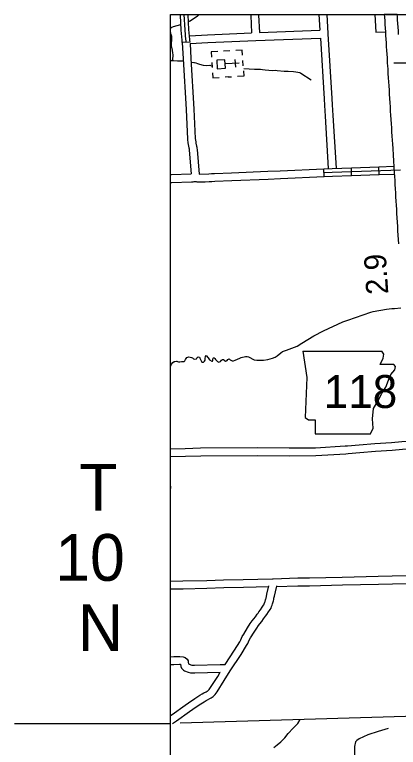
# Model space of a CAD drawing. Extents: x -117616 to 64730, y 54117 to 789866.
# Drawn here: x 62287.4 to 62435.1, y 55033 to 55314.9 of the extents above; entities that cross this region are included whole.
import ezdxf

# ---------------------------------------------------------------- set-up
doc = ezdxf.new("R2010")
doc.units = 0
for name, color, linetype in [('35', 7, 'Continuous'), ('43', 7, 'Continuous'), ('Default', 7, 'Continuous'), ('Level 10', 7, 'Continuous'), ('Level 2', 7, 'Continuous'), ('Level 21', 7, 'Continuous'), ('Level 32', 7, 'Continuous'), ('Level 35', 7, 'Continuous'), ('Level 45', 7, 'Continuous'), ('Level 46', 7, 'Continuous'), ('Level 48', 7, 'Continuous'), ('Level 57', 7, 'Continuous'), ('Level 6', 7, 'Continuous'), ('R_Dimension', 7, 'Continuous'), ('R_No Plot', 7, 'Continuous')]:
    doc.layers.add(name, color=color, linetype=linetype)

msp = doc.modelspace()

# ---------------------------------------------------------------- linework, layer by layer
at = {"layer": '35'}
msp.add_lwpolyline([(62387.21, 55032.85), (62388.44, 55033.94), (62389.9, 55035.12), (62391.39, 55036.58), (62392.73, 55038.32), (62394.67, 55040.29), (62396.38, 55042.14), (62397.36, 55043.64)], dxfattribs=at)
at = {"layer": '43'}
for points in [[(62431.16, 55040.24), (62427.33, 55039.1), (62423.42, 55037.8), (62419.97, 55036.2), (62419.09, 55035.65), (62418.63, 55035.06), (62418.29, 55033.25), (62418.41, 55024.66), (62418.79, 55018.94), (62418.58, 55015.87), (62418.46, 55014.9), (62416.31, 55011.99), (62414.54, 55009.97), (62411.18, 55007.03), (62408.53, 55004.54), (62407.15, 55003.45), (62405.85, 55002.79), (62404.15, 55001.88), (62398.15, 54997.89), (62394.95, 54995.54), (62387.25, 54990.19)], [(62424.86, 55038.28), (62423.42, 55037.8), (62419.97, 55036.2), (62419.09, 55035.65), (62418.63, 55035.06), (62418.48, 55034.26)], [(62431.16, 55040.24), (62427.36, 55039.11)]]:
    msp.add_lwpolyline(points, dxfattribs=at)
at = {"layer": 'Default'}
msp.add_lwpolyline([(62347.42, 55132.13), (62347.44, 55132.23), (62347.5, 55132.67), (62347.48, 55133.52)], dxfattribs=at)
at = {"layer": 'Level 10'}
for p, q in [((62434.72, 55314.94), (62429.71, 55314.94)), ((62429.71, 55314.94), (62429.77, 55313.98)), ((62434.76, 55314.29), (62434.72, 55314.94)), ((62434.84, 55312.9), (62434.76, 55314.29)), ((62429.77, 55313.98), (62429.85, 55312.59)), ((62429.85, 55312.59), (62429.94, 55311.18)), ((62434.93, 55311.5), (62434.84, 55312.9)), ((62435.02, 55310.09), (62434.93, 55311.5)), ((62429.94, 55311.18), (62430.03, 55309.78)), ((62430.03, 55309.78), (62430.12, 55308.36)), ((62435.11, 55308.67), (62435.02, 55310.09)), ((62435.19, 55307.25), (62435.11, 55308.67)), ((62430.12, 55308.36), (62430.2, 55306.95)), ((62430.2, 55306.95), (62430.29, 55305.51)), ((62430.29, 55305.51), (62430.38, 55304.08)), ((62430.38, 55304.08), (62430.47, 55302.63)), ((62430.47, 55302.63), (62430.57, 55301.19)), ((62430.57, 55301.19), (62430.66, 55299.73)), ((62430.66, 55299.73), (62430.75, 55298.27)), ((62430.75, 55298.27), (62430.84, 55296.8)), ((62430.84, 55296.8), (62430.87, 55296.14)), ((62430.87, 55296.14), (62430.92, 55295.31)), ((62430.92, 55295.31), (62431.01, 55293.78)), ((62431.01, 55293.78), (62431.11, 55292.24)), ((62431.11, 55292.24), (62431.22, 55290.67)), ((62431.22, 55290.67), (62431.32, 55289.1)), ((62431.32, 55289.1), (62431.43, 55287.51)), ((62431.43, 55287.51), (62431.53, 55285.9)), ((62431.53, 55285.9), (62431.63, 55284.28)), ((62431.63, 55284.28), (62431.72, 55282.66)), ((62431.72, 55282.66), (62431.82, 55281.05)), ((62431.82, 55281.05), (62431.92, 55279.43)), ((62431.92, 55279.43), (62432.01, 55277.81)), ((62432.01, 55277.81), (62432.12, 55276.2)), ((62432.12, 55276.2), (62432.22, 55274.58)), ((62432.22, 55274.58), (62432.33, 55272.98)), ((62432.33, 55272.98), (62432.43, 55271.39)), ((62432.43, 55271.39), (62432.53, 55269.8)), ((62432.53, 55269.8), (62432.63, 55268.22)), ((62432.63, 55268.22), (62432.73, 55266.65)), ((62432.73, 55266.65), (62432.83, 55265.09)), ((62432.83, 55265.09), (62432.94, 55263.41)), ((62432.94, 55263.41), (62433.11, 55260.83)), ((62433.11, 55260.83), (62433.51, 55254.19)), ((62433.51, 55254.19), (62433.61, 55252.63)), ((62433.61, 55252.63), (62433.7, 55251.07)), ((62433.7, 55251.07), (62433.8, 55249.51)), ((62433.8, 55249.51), (62433.89, 55247.94)), ((62433.89, 55247.94), (62433.98, 55246.36)), ((62433.98, 55246.36), (62434.07, 55244.77)), ((62434.07, 55244.77), (62434.17, 55243.18)), ((62434.17, 55243.18), (62434.26, 55241.58)), ((62434.26, 55241.58), (62434.35, 55239.97)), ((62434.35, 55239.97), (62434.44, 55238.37)), ((62434.44, 55238.37), (62434.53, 55236.75)), ((62434.53, 55236.75), (62434.63, 55235.11)), ((62434.63, 55235.11), (62434.73, 55233.46)), ((62434.73, 55233.46), (62434.83, 55231.79)), ((62434.83, 55231.79), (62434.94, 55230.11)), ((62434.94, 55230.11), (62435.04, 55228.42)), ((62435.04, 55228.42), (62435.13, 55226.73))]:
    msp.add_line(p, q, dxfattribs=at)
at = {"layer": 'Level 2'}
msp.add_lwpolyline([(62442.23, 55045.01), (62351.19, 55042.23)], dxfattribs=at)
at = {"layer": 'Level 21'}
for p, q in [((62398.37, 55185.4), (62399.89, 55175.25)), ((62429.5, 55184.22), (62428.8, 55185.39)), ((62428.15, 55180.33), (62429.33, 55182.69)), ((62429.33, 55182.69), (62429.5, 55184.22)), ((62433.39, 55180.33), (62428.15, 55180.33)), ((62434.07, 55179.48), (62433.39, 55180.33)), ((62433.73, 55178.3), (62434.07, 55179.48)), ((62431.36, 55174.24), (62432.21, 55176.44)), ((62432.21, 55176.44), (62433.73, 55178.3)), ((62399.89, 55175.25), (62399.22, 55159.86)), ((62430.34, 55171.53), (62431.36, 55174.24)), ((62428.65, 55168.99), (62430.34, 55171.53)), ((62427.47, 55166.62), (62428.65, 55168.99)), ((62425.61, 55163.41), (62427.47, 55166.62)), ((62425.1, 55159.35), (62425.61, 55163.41)), ((62399.22, 55159.86), (62400.57, 55159.01)), ((62425.44, 55155.8), (62425.1, 55159.35)), ((62400.57, 55159.01), (62403.11, 55159.01)), ((62403.11, 55159.01), (62403.11, 55153.6)), ((62403.11, 55153.6), (62424.42, 55153.6)), ((62424.42, 55153.6), (62425.44, 55155.8))]:
    msp.add_line(p, q, dxfattribs=at)
msp.add_lwpolyline([(62398.37, 55185.4), (62428.8, 55185.39)], dxfattribs=at)
at = {"layer": 'Level 32'}
for p, q in [((62354.2, 55314.91), (62351.2, 55314.73)), ((62354.94, 55304.39), (62351.95, 55304.18)), ((62406.57, 55252.65), (62406.46, 55255.64)), ((62417.12, 55253.02), (62417.02, 55256.02)), ((62427.68, 55253.4), (62427.57, 55256.4))]:
    msp.add_line(p, q, dxfattribs=at)
for points in [[(62351.2, 55314.73), (62351.19, 55314.94)], [(62351.95, 55304.18), (62351.89, 55304.91), (62351.88, 55305.09), (62351.54, 55309), (62351.2, 55314.73)], [(62353.44, 55304.28), (62353.39, 55305.02), (62353.37, 55305.2), (62353.04, 55309.1), (62352.69, 55314.94)], [(62354.2, 55314.91), (62354.2, 55314.94)], [(62354.94, 55304.39), (62354.88, 55305.12), (62354.87, 55305.32), (62354.53, 55309.21), (62354.2, 55314.91)], [(62406.46, 55255.64), (62409.63, 55255.76), (62417.02, 55256.02)], [(62406.52, 55254.14), (62409.69, 55254.26), (62435.95, 55255.19)], [(62417.02, 55256.02), (62427.57, 55256.4)], [(62427.57, 55256.4), (62433.36, 55256.6)], [(62406.57, 55252.65), (62409.74, 55252.76), (62417.12, 55253.02)], [(62417.12, 55253.02), (62427.68, 55253.4)], [(62427.68, 55253.4), (62433.55, 55253.61)]]:
    msp.add_lwpolyline(points, dxfattribs=at)
at = {"layer": 'Level 35'}
for points in [[(62358.44, 55314.94), (62357.83, 55314.39), (62354.93, 55312.41), (62354.27, 55312.15)], [(62351.26, 55311.07), (62348.44, 55310.19), (62348.13, 55310.1), (62347.8, 55309.94), (62347.42, 55309.64)], [(62347.42, 55308.04), (62347.47, 55307.67), (62347.67, 55306.98), (62347.74, 55306.7), (62347.82, 55305.6), (62347.74, 55304.71), (62347.67, 55304.21), (62347.67, 55304.15), (62347.67, 55302.9), (62347.99, 55301.33), (62348.23, 55300.14), (62348.3, 55299.6), (62348.31, 55299.36), (62348.13, 55297.74), (62347.99, 55297.28)], [(62347.42, 55297.33), (62347.48, 55297.33), (62348.6, 55297.31), (62350.08, 55297.2), (62351.87, 55297.11), (62352.32, 55297.04)], [(62355.36, 55296.66), (62356.39, 55296.58), (62356.71, 55296.58), (62357.14, 55296.42), (62357.81, 55296.13), (62358.63, 55295.87), (62359.96, 55295.52), (62361.45, 55295.43), (62362.57, 55295.47), (62363.21, 55295.27)], [(62375.67, 55294.22), (62379.76, 55293.92), (62382, 55293.91), (62382.82, 55293.81), (62383.79, 55293.72), (62386.66, 55293.46), (62387.72, 55293.54), (62388.52, 55293.42), (62391.22, 55293.13), (62392.76, 55293.15), (62394.72, 55293.03), (62395.66, 55292.96), (62397.24, 55292.62), (62397.59, 55292.39), (62401.52, 55289.82)], [(62377.39, 55183.2), (62379.65, 55182.13), (62380.66, 55181.9), (62381.74, 55181.9), (62383.27, 55182), (62384.9, 55182.26), (62386.68, 55182.69), (62387.66, 55183.09), (62388.51, 55183.69), (62389.91, 55184.84), (62390.51, 55185.26), (62392.1, 55185.84), (62396.14, 55187.37), (62397.96, 55188.55), (62402.56, 55191.31), (62406.27, 55193.27), (62413.78, 55196.71), (62415.61, 55197.32), (62424.55, 55200.41), (62425.46, 55200.64), (62430.61, 55201.54), (62432.61, 55201.82), (62433.67, 55201.88), (62436.12, 55202.15)], [(62347.42, 55179.68), (62347.55, 55179.83), (62347.82, 55180.41), (62348.27, 55181.1), (62348.77, 55181.4), (62349.03, 55181.46), (62349.09, 55181.46), (62349.67, 55181.53), (62349.91, 55181.52), (62350.15, 55181.47), (62350.53, 55181.37), (62351.02, 55181.32), (62351.59, 55181.39), (62352.63, 55181.48), (62352.96, 55181.7), (62353.21, 55182.19), (62353.41, 55182.58), (62353.67, 55182.94), (62354.42, 55183.22), (62354.98, 55183.17), (62355.49, 55183.03), (62355.84, 55182.83), (62356.3, 55182.47), (62356.7, 55182.33), (62357.45, 55182.53), (62357.71, 55182.98), (62358.07, 55183.3), (62358.54, 55183.07), (62358.76, 55182.72), (62359.1, 55181.97), (62359.5, 55181.21), (62360.06, 55181.13), (62360.54, 55181.52), (62360.78, 55181.99), (62360.77, 55182.58), (62360.89, 55183.43), (62361.19, 55183.72), (62361.87, 55182.85), (62362.16, 55182.43), (62362.43, 55182.1), (62363.32, 55181.58), (62363.52, 55181.61), (62363.65, 55181.82), (62363.73, 55182.08), (62363.75, 55182.47), (62363.84, 55182.77), (62363.99, 55182.88), (62364.22, 55182.83), (62364.49, 55182.59), (62364.73, 55182.22), (62365.55, 55181.41), (62366.06, 55181.24), (62366.61, 55181.41), (62367.08, 55181.93), (62367.47, 55182.19), (62367.79, 55182.17), (62368.06, 55181.92), (62368.6, 55181.57), (62368.91, 55181.65), (62369.28, 55181.89), (62369.52, 55182.22), (62369.74, 55182.41), (62369.95, 55182.5), (62370.16, 55182.31), (62370.43, 55182.04), (62371.09, 55181.74), (62371.65, 55181.68), (62372.28, 55181.9), (62374.08, 55182.77), (62374.55, 55182.94), (62375.1, 55183.11), (62375.73, 55183.24), (62376.27, 55183.34), (62376.87, 55183.36), (62377.39, 55183.2)]]:
    msp.add_lwpolyline(points, dxfattribs=at)
at = {"layer": 'Level 45'}
msp.add_lwpolyline([(62464.93, 55295.25), (62451.13, 55295.1), (62450.31, 55295.2), (62449.69, 55295.41), (62449.38, 55295.46), (62448.6, 55295.93), (62447.77, 55296.29), (62446.95, 55296.44), (62445.71, 55296.55), (62444.36, 55296.5), (62442.76, 55296.44), (62439.76, 55296.29), (62437.44, 55296.29), (62433.37, 55296.29)], dxfattribs=at)
at = {"layer": 'Level 46'}
for points in [[(62378.26, 55314.94), (62378.28, 55314.6), (62378.65, 55307.9)], [(62381.27, 55314.94), (62381.27, 55314.74), (62381.65, 55308.02)], [(62404.53, 55314.94), (62404.91, 55308.94)], [(62407.54, 55314.94), (62407.99, 55307.72), (62408, 55307.6), (62409.55, 55282.71), (62409.67, 55280.2), (62409.95, 55276.11), (62411.13, 55255.81)], [(62381.65, 55308.02), (62404.91, 55308.94)], [(62354.74, 55306.83), (62361.68, 55307.23), (62378.65, 55307.9)], [(62354.97, 55303.84), (62361.83, 55304.23), (62380.29, 55304.97), (62405.1, 55305.95)], [(62405.1, 55305.95), (62406.56, 55282.54), (62406.67, 55280.03), (62406.95, 55275.92), (62408.13, 55255.7)], [(62351.94, 55304.2), (62352.28, 55297.95), (62353.43, 55278.39), (62353.93, 55267.03), (62354.13, 55265.52), (62354.19, 55265.21), (62354.23, 55264.91), (62354.52, 55263.62), (62354.59, 55263.35), (62354.6, 55263.23), (62354.64, 55262.83), (62355.38, 55253.62)], [(62354.97, 55303.84), (62355.28, 55298.12), (62356.43, 55278.55), (62356.92, 55267.3), (62357.1, 55265.98), (62357.15, 55265.66), (62357.18, 55265.44), (62357.45, 55264.3), (62357.54, 55263.9), (62357.58, 55263.58), (62357.63, 55263.1), (62358.4, 55253.53)], [(62358.42, 55253.53), (62362.23, 55253.71), (62363.23, 55253.75), (62364.29, 55253.81), (62370.9, 55254.12), (62384.94, 55254.66), (62389.59, 55254.85), (62406.46, 55255.64)], [(62347.42, 55253.34), (62347.83, 55253.36), (62355.38, 55253.62)], [(62347.42, 55250.34), (62347.92, 55250.36), (62355.55, 55250.63), (62355.76, 55250.64), (62356.11, 55250.64), (62356.56, 55250.67), (62356.99, 55250.7), (62357.33, 55250.67), (62357.57, 55250.65), (62358.31, 55250.62), (62359.34, 55250.64), (62360.81, 55250.64), (62362.34, 55250.71), (62363.37, 55250.75), (62364.42, 55250.82), (62371.02, 55251.12), (62385.04, 55251.66), (62389.7, 55251.85), (62406.59, 55252.65)], [(62347.42, 55147.85), (62353.08, 55147.99), (62359, 55148.17), (62381.04, 55148.33), (62393.09, 55148.18), (62403.23, 55148.22), (62414.69, 55148.94), (62415.54, 55149.03), (62420.05, 55149.4), (62426.03, 55149.88), (62432.45, 55150.33), (62436.43, 55150.65), (62439.67, 55150.96)], [(62347.42, 55144.85), (62353.16, 55144.99), (62359.06, 55145.18), (62381.03, 55145.33), (62393.07, 55145.18), (62403.33, 55145.22), (62414.94, 55145.95), (62415.81, 55146.04), (62420.29, 55146.41), (62426.26, 55146.89), (62432.67, 55147.34), (62436.69, 55147.66), (62439.84, 55147.96)], [(62347.42, 55096.91), (62352.18, 55096.99), (62361.38, 55097.19), (62367.87, 55097.41), (62375.4, 55097.6), (62386.68, 55097.83), (62386.89, 55097.84), (62396.42, 55098.14), (62400.85, 55098.14), (62413.52, 55098.47), (62427.36, 55098.77), (62438.15, 55099.04), (62442.24, 55099.19), (62442.61, 55099.2)], [(62347.42, 55093.91), (62352.24, 55093.99), (62361.46, 55094.19), (62367.96, 55094.41), (62375.47, 55094.6), (62385.32, 55094.81)], [(62348.19, 55042.14), (62349.75, 55043.17), (62354.74, 55046.76), (62356, 55047.6), (62358.43, 55049.25), (62360.31, 55050.5), (62361.14, 55050.99), (62361.59, 55051.24), (62362.5, 55051.7), (62363.08, 55052.02), (62363.78, 55052.51), (62363.92, 55052.67), (62364.12, 55052.78), (62364.61, 55053.33), (62365.32, 55054.31), (62368.12, 55058.68), (62370.36, 55062.38), (62374.61, 55068.69), (62376.65, 55072.1), (62377.12, 55072.95), (62377.71, 55074.15), (62378.24, 55075.06), (62379.58, 55077.33), (62380.59, 55078.88), (62381.29, 55079.8), (62381.85, 55080.55), (62382.52, 55081.44), (62383.24, 55082.4), (62383.61, 55082.9), (62383.95, 55083.42), (62384.43, 55084.1), (62385.19, 55085.13), (62385.53, 55085.65), (62385.76, 55086.04), (62386.1, 55086.54), (62386.27, 55087.13), (62386.52, 55087.69), (62386.72, 55088.24), (62386.93, 55088.99), (62387, 55089.31), (62387.14, 55089.79), (62387.23, 55090.41), (62387.43, 55091.12), (62388.25, 55094.51), (62388.4, 55095.01), (62388.41, 55095.16)], [(62368.39, 55064.83), (62372.08, 55070.3), (62374.05, 55073.59), (62374.46, 55074.33), (62375.06, 55075.56), (62375.65, 55076.57), (62377.03, 55078.92), (62378.14, 55080.61), (62378.89, 55081.6), (62379.45, 55082.35), (62380.12, 55083.24), (62380.83, 55084.19), (62381.15, 55084.62), (62381.47, 55085.1), (62381.99, 55085.85), (62382.73, 55086.85), (62383, 55087.26), (62383.23, 55087.64), (62383.35, 55087.82), (62383.45, 55088.17), (62383.73, 55088.8), (62383.85, 55089.13), (62384.03, 55089.76), (62384.1, 55090.06), (62384.2, 55090.42), (62384.3, 55091.04), (62384.52, 55091.87), (62385.3, 55095.08)], [(62388.05, 55094.88), (62396.47, 55095.14), (62400.89, 55095.14), (62413.59, 55095.47), (62427.43, 55095.77), (62438.24, 55096.04), (62442.32, 55096.19), (62442.67, 55096.2)], [(62347.42, 55067.85), (62348.65, 55067.88), (62351.01, 55067.93), (62352.29, 55067.84), (62353.12, 55067.58), (62353.88, 55066.95), (62354.23, 55066.26), (62354.27, 55065.79), (62354.3, 55065.07), (62355.22, 55064.71), (62355.58, 55064.61), (62355.77, 55064.59), (62356.09, 55064.6), (62356.6, 55064.64), (62366.5, 55064.83), (62367.54, 55064.83), (62368.39, 55064.83)], [(62347.42, 55064.85), (62348.73, 55064.88), (62350.94, 55064.93), (62351.3, 55064.91), (62351.34, 55064.03), (62351.69, 55063.37), (62351.97, 55063.07), (62352.4, 55062.7), (62352.83, 55062.42), (62354.27, 55061.86), (62355.05, 55061.64), (62355.68, 55061.59), (62356.24, 55061.61), (62356.73, 55061.64), (62366.52, 55061.83)], [(62347.42, 55045.23), (62348.04, 55045.64), (62353.03, 55049.23), (62354.33, 55050.1), (62356.76, 55051.74), (62358.72, 55053.04), (62359.65, 55053.59), (62360.18, 55053.89), (62361.09, 55054.35), (62361.49, 55054.57), (62361.76, 55054.76), (62361.98, 55055.02), (62362.21, 55055.15), (62362.27, 55055.21), (62362.84, 55056), (62365.57, 55060.27), (62366.52, 55061.83)]]:
    msp.add_lwpolyline(points, dxfattribs=at)
at = {"layer": 'Level 57'}
for p, q in [((62370.3, 55301), (62367.8, 55300.86)), ((62372.21, 55297.67), (62372.39, 55294.68)), ((62363.31, 55296.58), (62363.43, 55294.58)), ((62373.8, 55296.26), (62368.42, 55295.95)), ((62375.41, 55295.28), (62375.29, 55297.28)), ((62369.65, 55290.95), (62368.39, 55290.87)), ((62369.65, 55290.95), (62370.88, 55291.02))]:
    msp.add_line(p, q, dxfattribs=at)
for points in [[(62365.57, 55300.73), (62363.08, 55300.58), (62363.19, 55298.58)], [(62375.17, 55299.29), (62375.06, 55301.28), (62372.56, 55301.14)], [(62363.55, 55292.59), (62363.66, 55290.6), (62366.16, 55290.74)], [(62375.53, 55293.3), (62375.64, 55291.3), (62373.15, 55291.15)]]:
    msp.add_lwpolyline(points, dxfattribs=at)
msp.add_lwpolyline([(62365.4, 55294.15), (62368.52, 55294.34), (62368.33, 55297.57), (62365.21, 55297.38)], close=True, dxfattribs=at)
at = {"layer": 'Level 6'}
for points in [[(62426.06, 55314.94), (62426.42, 55308.2)], [(62426.42, 55308.2), (62430.06, 55308.35)]]:
    msp.add_lwpolyline(points, dxfattribs=at)
at = {"layer": 'R_Dimension'}
msp.add_line((62287.42, 55042.12), (62347.42, 55042.11), dxfattribs=at)
at = {"layer": 'R_No Plot'}
msp.add_lwpolyline([(62347.42, 55314.94), (63854.85, 55314.94), (63854.85, 54389.3), (62347.42, 54389.3)], close=True, dxfattribs=at)

# ---------------------------------------------------------------- texts
at = {"layer": 'Default'}
for s, p in [('T', (62312.27, 55124.04)), ('10', (62303.05, 55097.04)), ('N', (62311.76, 55070.04))]:
    msp.add_text(s, height=18, dxfattribs=at).set_placement(p)
at = {"layer": 'Level 21'}
msp.add_text('118', height=12.672, dxfattribs=at).set_placement((62406.4, 55163.56))
at = {"layer": 'Level 48'}
msp.add_text('2.9', height=8.448, rotation=93.8064, dxfattribs=at).set_placement((62431.28, 55207.47))

doc.saveas('drawing.dxf')
